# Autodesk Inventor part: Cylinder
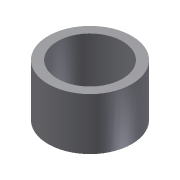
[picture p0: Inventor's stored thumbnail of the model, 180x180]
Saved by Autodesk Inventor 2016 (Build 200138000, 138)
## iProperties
Shininess: 64.0
Length Units: 11269
Angle Units: 11279
Time Units: 11290
Mass Units: 11283
Length Display Precision: 3
Angle Display Precision: 2
Compacted: True
Part Number: Cylinder
Document SubType Name: Modeling
Created: 2003-01
Designer: Owner
Density: 1 g/cm^3
Material: Generic
Appearance: Default
Density: 0.0
Volumn: 0.0
Area: 0.0
PropertySet Name: Model Information
Control State: 0
Master: False
Checked Out: False
Author: Owner
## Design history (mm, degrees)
sketch "Sketch1"
  geometry: C1 r 112.5 at (0, 0); C2 r 87.5 at (0, 0)
  constraints: 2 centre point, 1 coincident, 1 concentric
  dimensions: "d0" = 225 diameter of C1; "d1" = 175 diameter of C2
extrude "Extrusion1" new body sketch "Sketch1" stored distance "d2" = 140; taper "d3" = 0 deg
body "Solid1"
